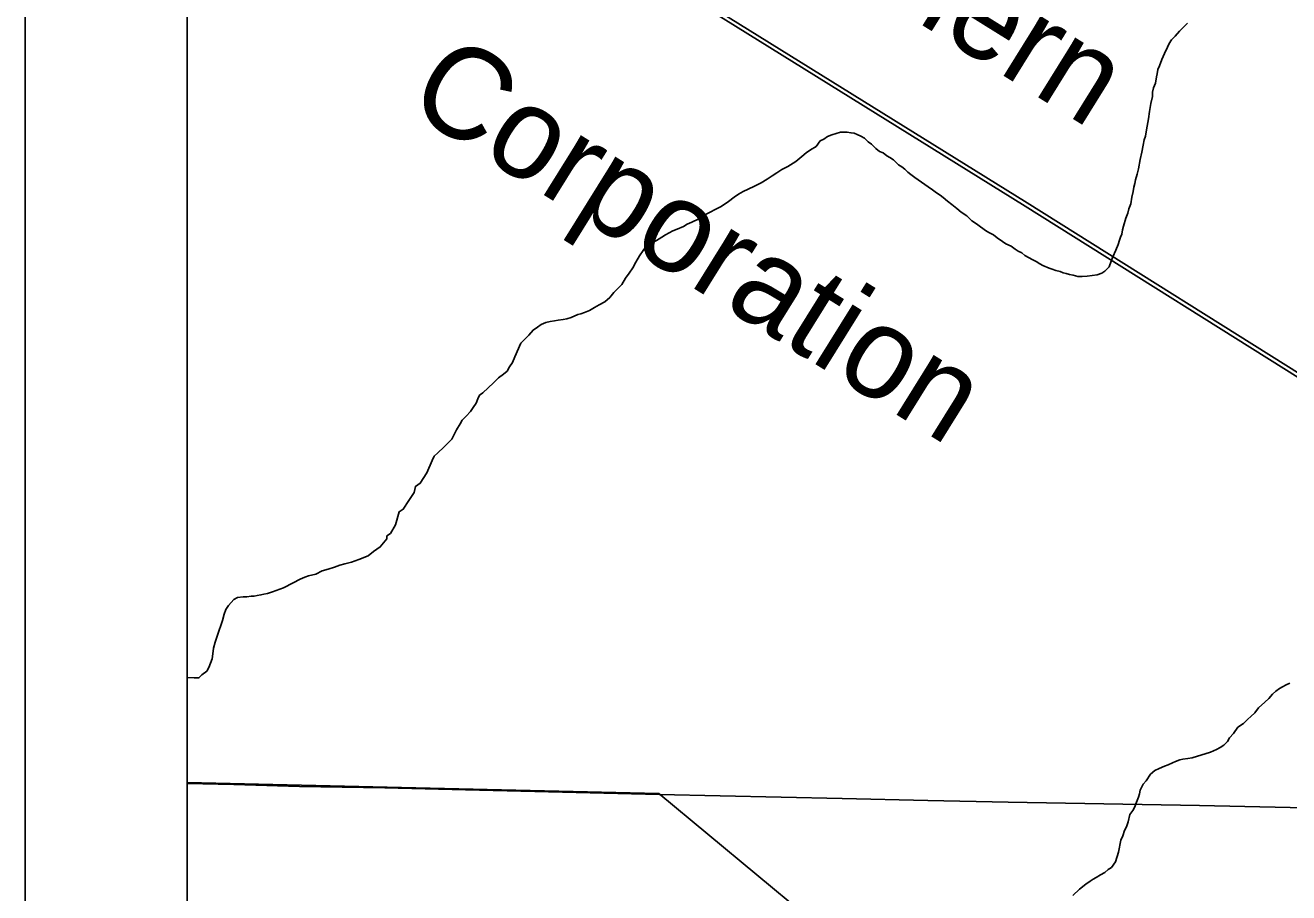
# Model space of a CAD drawing. Extents: x 0 to 34, y 0 to 22.
# Drawn here: x 2 to 2.781, y 18.953 to 19.488 of the extents above; entities that cross this region are included whole.
import ezdxf

# ---------------------------------------------------------------- set-up
doc = ezdxf.new("R2010")
doc.units = 0
for name, color, linetype in [('GM_X_Corporation', 7, 'Continuous'), ('GM_X_County_Road', 7, 'Continuous'), ('GM_X_Minor_River', 7, 'Continuous'), ('GM_X_Rail_Line', 7, 'Continuous'), ('GM_X_Rail_Line_Text', 7, 'Continuous'), ('SH_Data', 7, 'Continuous')]:
    doc.layers.add(name, color=color, linetype=linetype)

msp = doc.modelspace()

# ---------------------------------------------------------------- linework, layer by layer
at = {"layer": 'GM_X_Corporation'}
for points in [[(2.1, 20.70886), (2.1, 14.1)], [(2.1, 20.70886), (2.1, 19.02062), (2.39144, 19.01387), (3.23918, 18.31062), (3.2398, 18.29194), (3.237, 18.24766), (3.22868, 18.20949), (3.22161, 18.17707), (3.2145, 18.15536), (3.24994, 18.15447), (3.27387, 18.15297), (3.39885, 18.15061), (3.6928, 17.93671), (3.75574, 17.93543), (3.84884, 17.86912), (3.84285, 17.86087), (3.98096, 17.87502), (3.9776, 17.90801), (3.97403, 17.90765), (3.97127, 17.92381), (4.7767, 17.9112)], [(2.1, 20.70886), (2.1, 16.88936)]]:
    msp.add_lwpolyline(points, dxfattribs=at)
at = {"layer": 'GM_X_County_Road'}
msp.add_line((2.27203, 19.01615), (2.39165, 19.01331), dxfattribs=at)
for points in [[(2.1, 19.02008), (2.12897, 19.01942), (2.16935, 19.01834), (2.22219, 19.01733), (2.27203, 19.01615)], [(2.39165, 19.01331), (2.50479, 19.01089), (2.55763, 19.00957), (2.60739, 19.00864), (2.72555, 19.00647), (2.7815, 19.00523), (2.83189, 19.00411), (2.84857, 19.00373), (2.87789, 19.00307), (3.06757, 18.99891), (3.18347, 18.99648)]]:
    msp.add_lwpolyline(points, dxfattribs=at)
at = {"layer": 'GM_X_Minor_River'}
for points in [[(2.71812, 19.48984), (2.71586, 19.48754), (2.71323, 19.48485), (2.7106, 19.48178), (2.70834, 19.47948), (2.70684, 19.47719), (2.70573, 19.4749), (2.70387, 19.47108), (2.70238, 19.46726), (2.7009, 19.46345), (2.69978, 19.46116), (2.69943, 19.45849), (2.69907, 19.45659), (2.69835, 19.45278), (2.69723, 19.44973), (2.6965, 19.44706), (2.69653, 19.4444), (2.69543, 19.44021), (2.69471, 19.43526), (2.694, 19.43069), (2.69328, 19.42612), (2.69256, 19.42269), (2.6922, 19.42003), (2.69147, 19.41774), (2.69074, 19.41431), (2.69002, 19.41012), (2.68892, 19.40555), (2.68784, 19.39984), (2.68711, 19.39641), (2.68601, 19.39298), (2.68565, 19.3907), (2.68491, 19.38841), (2.68456, 19.38574), (2.68383, 19.38232), (2.68311, 19.37813), (2.682, 19.37508), (2.68127, 19.37241), (2.68016, 19.36936), (2.67868, 19.3644), (2.67795, 19.36211), (2.67759, 19.35945), (2.67685, 19.35754), (2.67611, 19.35563), (2.67538, 19.35297), (2.67389, 19.34953), (2.67203, 19.34533), (2.67092, 19.34266), (2.66981, 19.33923), (2.66718, 19.33654), (2.66529, 19.33538), (2.66226, 19.33422), (2.65619, 19.3334), (2.65315, 19.33337), (2.65049, 19.33334), (2.64745, 19.33407), (2.64516, 19.33443), (2.64326, 19.33518), (2.64135, 19.33554), (2.63945, 19.33628), (2.63678, 19.33702), (2.63449, 19.33775), (2.63259, 19.3385), (2.62877, 19.33998), (2.62686, 19.3411), (2.62457, 19.3426), (2.62228, 19.34372), (2.62037, 19.34484), (2.61769, 19.34634), (2.61578, 19.34784), (2.61349, 19.34896), (2.61158, 19.35008), (2.60928, 19.35196), (2.60585, 19.35345), (2.60393, 19.35495), (2.60049, 19.3572)], [(2.60049, 19.3572), (2.59819, 19.35908), (2.5959, 19.3602), (2.59399, 19.36132), (2.59017, 19.36395), (2.58787, 19.36583), (2.58481, 19.3677), (2.58174, 19.37071), (2.5783, 19.37296), (2.57562, 19.37521), (2.57256, 19.37785), (2.56988, 19.37972), (2.5672, 19.38198), (2.56528, 19.38348), (2.56299, 19.38498), (2.56069, 19.38686), (2.55801, 19.38873), (2.5496, 19.39436), (2.5473, 19.39623), (2.54539, 19.39774), (2.54347, 19.39962), (2.54156, 19.40112), (2.53964, 19.40224), (2.53658, 19.40526), (2.53428, 19.40675), (2.53237, 19.40788), (2.53007, 19.40976), (2.52779, 19.41049), (2.52549, 19.41237), (2.5228, 19.41501), (2.52089, 19.41651), (2.51859, 19.41877), (2.5163, 19.41989), (2.51401, 19.42101), (2.5121, 19.42175), (2.5102, 19.42211), (2.50791, 19.42247), (2.50601, 19.42245), (2.50374, 19.42243), (2.50108, 19.42165), (2.49843, 19.42086), (2.49578, 19.4197), (2.49352, 19.41816), (2.49125, 19.41699), (2.48862, 19.41355), (2.48522, 19.41161), (2.48258, 19.40969), (2.47994, 19.40738), (2.47617, 19.40431), (2.47127, 19.40122), (2.46749, 19.39928), (2.46446, 19.39735), (2.46144, 19.39542), (2.45842, 19.39349), (2.45465, 19.39118), (2.45011, 19.38886), (2.44368, 19.38575), (2.44066, 19.3842), (2.43802, 19.38228), (2.43462, 19.37958), (2.43009, 19.3765), (2.41951, 19.37108), (2.41573, 19.36876), (2.41195, 19.36683), (2.40892, 19.36566), (2.40666, 19.36412), (2.40287, 19.36256), (2.40022, 19.36139), (2.39796, 19.36023), (2.39569, 19.35907), (2.39342, 19.35753), (2.39002, 19.35559), (2.38738, 19.35405), (2.38549, 19.35251), (2.38323, 19.35135), (2.38172, 19.34944), (2.37948, 19.34599), (2.37724, 19.34217), (2.37537, 19.33873), (2.37312, 19.33529), (2.37087, 19.33223), (2.36863, 19.3284), (2.36562, 19.32533), (2.36374, 19.32341), (2.36111, 19.32035), (2.3581, 19.31766), (2.3547, 19.31573), (2.35167, 19.31418), (2.34865, 19.31225), (2.34562, 19.31108), (2.34335, 19.3103), (2.34146, 19.3099), (2.33729, 19.30796), (2.33464, 19.30718), (2.33237, 19.30677), (2.32933, 19.30636), (2.32706, 19.30596), (2.3244, 19.30556), (2.32175, 19.30477), (2.31872, 19.3036), (2.31646, 19.30206)], [(2.31646, 19.30206), (2.31381, 19.30014), (2.31118, 19.29707), (2.30817, 19.294), (2.30629, 19.29208), (2.30258, 19.28369), (2.30109, 19.28025), (2.29922, 19.27757), (2.29772, 19.2749), (2.29546, 19.27297), (2.29244, 19.27066), (2.28943, 19.26759), (2.28604, 19.26452), (2.28265, 19.26145), (2.28077, 19.25991), (2.27965, 19.25762), (2.27854, 19.25495), (2.27667, 19.25227), (2.27517, 19.24997), (2.27254, 19.24691), (2.2699, 19.2446), (2.26878, 19.24231), (2.26654, 19.23849), (2.26356, 19.23276), (2.25867, 19.22777), (2.2549, 19.22431), (2.25264, 19.22239), (2.25153, 19.21972), (2.24818, 19.21209), (2.24406, 19.20558), (2.24104, 19.20365), (2.24032, 19.19985), (2.23695, 19.19487), (2.23358, 19.18952), (2.23094, 19.18797), (2.22873, 19.17997), (2.22575, 19.17462), (2.22348, 19.17308), (2.2235, 19.17118), (2.21937, 19.1662), (2.21522, 19.1635), (2.21182, 19.1608), (2.20615, 19.15847), (2.2016, 19.1569), (2.19744, 19.15573), (2.1944, 19.15494), (2.19099, 19.15376), (2.18721, 19.15259), (2.18342, 19.15141), (2.17964, 19.14948), (2.17509, 19.14829), (2.17282, 19.14751), (2.16979, 19.14634), (2.16563, 19.14402), (2.15959, 19.14092), (2.15277, 19.13858), (2.14974, 19.13741), (2.14746, 19.13701), (2.14557, 19.13661), (2.14329, 19.13621), (2.1414, 19.13581), (2.1395, 19.13579), (2.13684, 19.13538), (2.13456, 19.13536), (2.13115, 19.13495), (2.12888, 19.13379), (2.1255, 19.12996), (2.124, 19.12766), (2.12289, 19.12461), (2.12179, 19.1208), (2.11884, 19.11165), (2.11736, 19.10745), (2.11625, 19.10364), (2.11591, 19.10022), (2.11556, 19.09717), (2.11444, 19.0945), (2.11333, 19.09183), (2.11221, 19.08954), (2.10919, 19.08723), (2.10731, 19.08531), (2.10427, 19.08528), (2.1, 19.0856)], [(2.73237, 19.03951), (2.73615, 19.04106), (2.73842, 19.04223), (2.74068, 19.04377), (2.74294, 19.04607), (2.74406, 19.04836), (2.74669, 19.05105), (2.74931, 19.05488), (2.75271, 19.05719), (2.75535, 19.05987), (2.75723, 19.06141), (2.75987, 19.06372), (2.76212, 19.06678), (2.76588, 19.07024), (2.76852, 19.07254), (2.77078, 19.07522), (2.77265, 19.07714), (2.77492, 19.07869), (2.77681, 19.07984), (2.77908, 19.081), (2.78134, 19.08217)], [(2.64736, 18.9509), (2.65151, 18.95474), (2.65528, 18.95781), (2.65792, 18.95974), (2.65981, 18.9609), (2.66169, 18.96206), (2.66434, 18.9636), (2.66698, 18.96515), (2.66924, 18.96707), (2.67113, 18.96823), (2.67376, 18.97167), (2.6756, 18.97777), (2.67705, 18.98501), (2.67816, 18.98768), (2.67927, 18.99111), (2.68039, 18.9934), (2.6815, 18.99645), (2.68259, 19.00103), (2.68447, 19.00332), (2.68559, 19.00562), (2.68633, 19.00752), (2.68781, 19.01172), (2.68855, 19.01363), (2.68891, 19.01591), (2.69077, 19.01973), (2.69265, 19.02165), (2.69527, 19.02585), (2.69791, 19.02816), (2.70056, 19.02933), (2.70396, 19.03088), (2.70623, 19.03166), (2.70888, 19.03283), (2.71077, 19.0336), (2.71342, 19.03477), (2.71531, 19.03517), (2.71835, 19.03557), (2.721, 19.03598), (2.73237, 19.03951)]]:
    msp.add_lwpolyline(points, dxfattribs=at)
at = {"layer": 'GM_X_Rail_Line'}
for points in [[(2.1, 19.70142), (2.16103, 19.66342), (2.61915, 19.37877), (2.80877, 19.25972), (2.87178, 19.22235), (2.91417, 19.19884), (2.96145, 19.17579), (3.00755, 19.15708), (3.04148, 19.14473), (3.06594, 19.13729), (3.09403, 19.1291), (3.1224, 19.12181), (3.14614, 19.11659), (3.15787, 19.11423), (3.17187, 19.11137), (3.1889, 19.10832), (3.21373, 19.10448), (3.28372, 19.09563), (3.58285, 19.05807), (3.80669, 19.02995), (3.91143, 19.01693), (3.99472, 19.00635), (4.05817, 18.99556)], [(2.1, 19.69867), (2.1598, 19.66145), (2.61791, 19.3768), (2.80755, 19.25774), (2.87061, 19.22033), (2.91309, 19.19678), (2.96049, 19.17367), (3.00671, 19.15491), (3.04073, 19.14252), (3.06527, 19.13506), (3.09341, 19.12686), (3.12186, 19.11955), (3.14566, 19.11432), (3.15741, 19.11195), (3.17143, 19.10908), (3.18852, 19.10602), (3.2134, 19.10217), (3.28342, 19.09332), (3.58256, 19.05576), (3.8064, 19.02764), (3.91114, 19.01462), (3.99437, 19.00405), (4.05773, 18.99328)]]:
    msp.add_lwpolyline(points, dxfattribs=at)
at = {"layer": 'SH_Data'}
for p, q in [((2, 21), (2, 14)), ((2.1, 20.9), (2.1, 14.1))]:
    msp.add_line(p, q, dxfattribs=at)

# ---------------------------------------------------------------- texts
at = {"layer": 'GM_X_Rail_Line_Text'}
for s, rotation, p in [('Norfolk Southern', 328.11923, (2.17472, 19.72456)), ('Corporation', 328.08515, (2.23385, 19.43753))]:
    msp.add_text(s, height=0.0566288, rotation=rotation, dxfattribs=at).set_placement(p)

doc.saveas('drawing.dxf')
